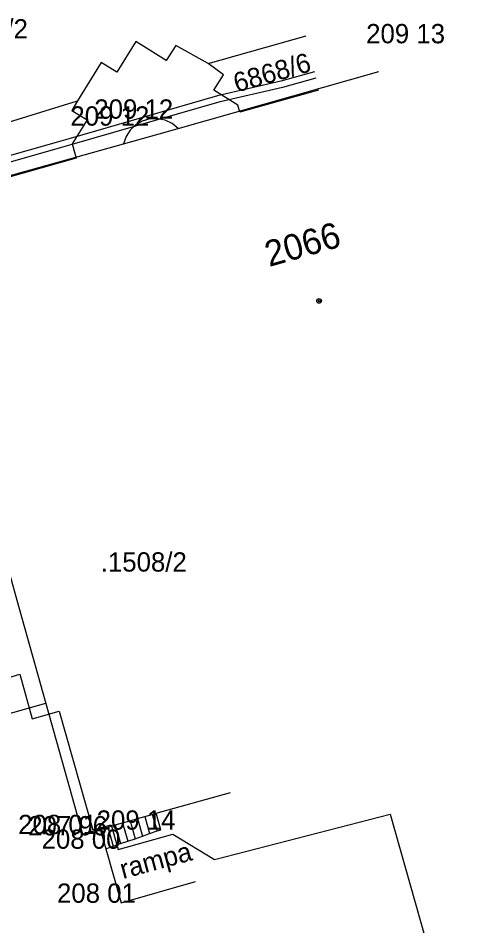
# Model space of a CAD drawing. Extents: x -524633 to -524336, y -1187893 to -1187683.
# Drawn here: x -524495.18 to -524477.19, y -1187799.22 to -1187763.94 of the extents above; entities that cross this region are included whole.
import ezdxf

# ---------------------------------------------------------------- set-up
doc = ezdxf.new("R2010")
doc.units = 0
for name, color, linetype in [('Hranice parcel', 7, 'Continuous'), ('Parcelní čísla', 7, 'Continuous'), ('Vrstva 1', 7, 'Continuous'), ('Vrstva 10', 7, 'Continuous'), ('Vrstva 11', 7, 'Continuous'), ('Vrstva 3', 7, 'Continuous'), ('Vrstva 39', 7, 'Continuous'), ('Vrstva 4', 7, 'Continuous'), ('Vrstva 41', 7, 'Continuous'), ('Vrstva 47', 7, 'Continuous'), ('Vrstva 5', 7, 'Continuous'), ('Vrstva 52', 7, 'Continuous'), ('Vrstva 54', 7, 'Continuous')]:
    doc.layers.add(name, color=color, linetype=linetype)

msp = doc.modelspace()

# ---------------------------------------------------------------- linework, layer by layer
at = {"layer": 'Hranice parcel'}
for points in [[(-524487.79, -1187765.71), (-524489.05, -1187765), (-524489.42, -1187765.59), (-524490.61, -1187764.85), (-524491.35, -1187766.04), (-524491.95, -1187765.67), (-524492.87, -1187767.16)], [(-524487.79, -1187765.71), (-524483.987, -1187764.63)], [(-524483.498, -1187766.741), (-524486.56, -1187767.6), (-524486.64, -1187767.32), (-524487.57, -1187766.74), (-524487.2, -1187766.14), (-524487.79, -1187765.71)], [(-524504.01, -1187770.49), (-524500.39, -1187769.48), (-524492.87, -1187767.16)], [(-524492.87, -1187767.16), (-524493.09, -1187767.53), (-524492.5, -1187767.9), (-524493.08, -1187768.83), (-524492.92, -1187769.39), (-524499.12, -1187771.13), (-524496.96, -1187778.81), (-524498.79, -1187779.32), (-524499.35, -1187780.04), (-524499.38, -1187780.95), (-524498.86, -1187781.65), (-524498.06, -1187781.92), (-524495.89, -1187789.67), (-524495.12, -1187789.44), (-524494.64, -1187791.17), (-524493.58, -1187790.87), (-524492.28, -1187795.49), (-524491.56, -1187795.29), (-524491.29, -1187796.25), (-524489.17, -1187795.65), (-524487.55, -1187796.64), (-524480.71, -1187794.88), (-524477.19, -1187807.33)]]:
    msp.add_lwpolyline(points, dxfattribs=at)
at = {"layer": 'Vrstva 1'}
for p, q in [((-524490.65, -1187768.12), (-524490.65, -1187768.12)), ((-524489.72, -1187767.85), (-524489.72, -1187767.85)), ((-524492.7, -1187795.63), (-524492.7, -1187795.63)), ((-524492.68, -1187795.65), (-524492.68, -1187795.65)), ((-524489.63, -1187795.48), (-524489.63, -1187795.48)), ((-524492.68, -1187795.7), (-524492.68, -1187795.7)), ((-524491.77, -1187796.22), (-524491.77, -1187796.22)), ((-524491.17, -1187798.32), (-524491.17, -1187798.32))]:
    msp.add_line(p, q, dxfattribs=at)
at = {"layer": 'Vrstva 10'}
msp.add_line((-524491.17, -1187798.32), (-524488.285, -1187797.496), dxfattribs=at)
msp.add_lwpolyline([(-524491.99, -1187795.46), (-524491.77, -1187796.22), (-524491.17, -1187798.32)], dxfattribs=at)
at = {"layer": 'Vrstva 11'}
for p, q in [((-524489.97, -1187794.89), (-524489.78, -1187795.53)), ((-524489.63, -1187795.48), (-524489.81, -1187794.84)), ((-524491.41, -1187795.29), (-524491.2, -1187796.02)), ((-524491.12, -1187795.21), (-524490.92, -1187795.93)), ((-524490.83, -1187795.13), (-524490.63, -1187795.83)), ((-524490.54, -1187795.05), (-524490.35, -1187795.73)), ((-524490.26, -1187794.97), (-524490.07, -1187795.63)), ((-524491.7, -1187795.38), (-524491.49, -1187796.12))]:
    msp.add_line(p, q, dxfattribs=at)
for points in [[(-524488.963, -1187768.228), (-524489.194, -1187768.037), (-524489.459, -1187767.911), (-524489.755, -1187767.85), (-524490.06, -1187767.859), (-524490.353, -1187767.941), (-524490.614, -1187768.092), (-524490.827, -1187768.296), (-524490.983, -1187768.541), (-524491.084, -1187768.83)], [(-524491.77, -1187796.22), (-524491.49, -1187796.12), (-524491.2, -1187796.02), (-524490.92, -1187795.93), (-524490.63, -1187795.83), (-524490.35, -1187795.73), (-524490.07, -1187795.63), (-524489.78, -1187795.53), (-524489.63, -1187795.48)]]:
    msp.add_lwpolyline(points, dxfattribs=at)
at = {"layer": 'Vrstva 39'}
for radius in [0.09, 0.0398]:
    msp.add_circle((-524483.48, -1187774.93), radius, dxfattribs=at)
at = {"layer": 'Vrstva 5'}
for points in [[(-524499.539, -1187771.22), (-524498.358, -1187770.855), (-524498.239, -1187770.82), (-524491.084, -1187768.83), (-524488.963, -1187768.228), (-524481.157, -1187766.012)], [(-524499.539, -1187771.22), (-524498.135, -1187776.222), (-524496.974, -1187780.356), (-524496.612, -1187781.644), (-524495.233, -1187786.556), (-524492.68, -1187795.65)], [(-524492.68, -1187795.65), (-524491.99, -1187795.46), (-524491.7, -1187795.38), (-524491.41, -1187795.29), (-524491.12, -1187795.21), (-524490.83, -1187795.13), (-524490.54, -1187795.05), (-524490.26, -1187794.97), (-524489.97, -1187794.89), (-524489.81, -1187794.84), (-524486.92, -1187794.03)]]:
    msp.add_lwpolyline(points, dxfattribs=at)
at = {"layer": 'Vrstva 52'}
for points in [[(-524483.663, -1187766.03), (-524484.962, -1187766.391), (-524487.429, -1187766.961), (-524493.162, -1187768.614), (-524493.613, -1187768.745), (-524498.093, -1187770.018), (-524499.562, -1187770.864), (-524500.075, -1187771.509), (-524500.024, -1187774.104), (-524500.526, -1187775.408), (-524503.594, -1187776.513), (-524503.908, -1187776.466), (-524505.014, -1187775.916)], [(-524483.606, -1187766.274), (-524484.9, -1187766.633), (-524487.373, -1187767.205), (-524493.092, -1187768.854), (-524493.544, -1187768.985), (-524497.995, -1187770.25), (-524499.396, -1187771.057), (-524499.823, -1187771.594), (-524499.773, -1187774.148), (-524500.334, -1187775.604), (-524503.568, -1187776.769), (-524503.945, -1187776.713), (-524504.936, -1187776.187)]]:
    msp.add_lwpolyline(points, dxfattribs=at)
at = {"layer": 'Vrstva 54'}
msp.add_line((-524506.175, -1187793.961), (-524494.102, -1187790.565), dxfattribs=at)

# ---------------------------------------------------------------- texts
at = {"layer": 'Parcelní čísla'}
for s, p in [('6868/2', (-524497.869, -1187764.733)), ('.1508/2', (-524491.969, -1187785.45))]:
    msp.add_text(s, height=0.75, dxfattribs=at).set_placement(p)
msp.add_text('6868/6', height=0.75, rotation=16, dxfattribs=at).set_placement((-524486.683, -1187766.837))
at = {"layer": 'Vrstva 3'}
for s, p in [('209 13 ', (-524481.65, -1187764.92)), ('209 12 ', (-524493.15, -1187768.12)), ('209 12 ', (-524492.22, -1187767.85)), ('208 01 ', (-524495.18, -1187795.65)), ('208 01 ', (-524493.67, -1187798.32))]:
    msp.add_text(s, height=0.75, dxfattribs=at).set_placement(p)
at = {"layer": 'Vrstva 4'}
for s, p in [('207.96', (-524494.791, -1187795.7)), ('209 14 ', (-524492.13, -1187795.48)), ('208 00 ', (-524494.27, -1187796.22))]:
    msp.add_text(s, height=0.75, dxfattribs=at).set_placement(p)
at = {"layer": 'Vrstva 41'}
msp.add_text('rampa', height=0.75, rotation=15.1892, dxfattribs=at).set_placement((-524491.107, -1187797.4))
at = {"layer": 'Vrstva 47'}
msp.add_text('2066', height=1, rotation=15.8828, dxfattribs=at).set_placement((-524485.423, -1187773.616))

doc.saveas('drawing.dxf')
